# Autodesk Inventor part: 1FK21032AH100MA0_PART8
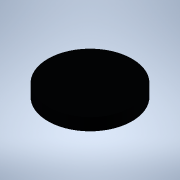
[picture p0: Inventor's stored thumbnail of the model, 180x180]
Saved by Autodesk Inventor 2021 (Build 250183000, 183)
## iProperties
Created: 2025-04
Part Number: 1FK21032AH100MA0_PART8
Material: Generic
Catalog Web Link: www.3dfindit.com
Description: -Servo synchronous motor
Document SubType Name: Modeling
Designer: psAdmin
Mass: 0.299142 g
Surface Area: 3.8585 cm^2
Volume: 0.299142 cm^3
Density: 1 g/cm^3
Appearance: PSOLRGB-38-46-56
Category: PARTsolutions
Title: 1FK21032AH100MA0_PART8
Author: Cadenas PARTsolutions
Comments: Servo synchronous motor
Sending System: PARTsolutions
Preprocessor: ST-DEVELOPER v19.3
PSOL_IDENT_0: {$CADENAS_DATA/23d-libs/siemens_ag/_cat_/12/33/1fk21032ah100ma0.prj},213 {VTYP=3D},{NB=1FK21032AH100
PSOL_IDENT_1: MA0_PART8},{LINA=1FK21032AH100MA0_PART8},{NN=1FK21032AH100MA0_PART8},{NOPRJ=TRUE},{DATE=19.08.2025 1
PSOL_IDENT_2: 4:00:27},{GEOMDATE=30.07.2025 02:02:58},{VERSION=},{LINEID=10},{WBVAR=},{WBNUMERIC=}  {NB=1FK21032AH
PSOL_IDENT_3: 100MA0_PART8},{LINA=1FK21032AH100MA0_PART8},{KT=DUMMY},{PREVIEW=../../../_pool_/d3/78/p_d211_xx_0093
PSOL_IDENT_4: 4j.png},{DESCSHORT=SIMOTICS S-1FK2 HD, SINAMICS S210 3AC 400V-480V, 0.59 Nm, 4500 rpm},{DESCLONG=SIM
PSOL_IDENT_5: OTICS S-1FK2 HD servo motor M0=0.64 Nm; PN = 0.28 kW at nN=4500 rpm (380-480 V); PN = 0.167 kW at nN=
PSOL_IDENT_6: 2500 rpm (200-240 V); with holding brake; degree of protection IP64; cylindrical shaft D14 x 30 mm;
PSOL_IDENT_7: absolute encoder 22-bit + 12-bit multiturn (encoder AM22DQC); with OCC interface; plug size M17, rot
PSOL_IDENT_8: atable; SIMOTICS S-1FK2 servomotorfor a wide range of uses in industrial environments. SIMOTICS S‑1F
PSOL_IDENT_9: K2 servomotors are compact synchronous motors with a high dynamic performance that set themselves ap
PSOL_IDENT_10: art as a result of their high power density, degree of protection and overload capability. The motor
PSOL_IDENT_11: s are available in two variants: as High Dynamic variant (highest dynamic performance as a result of
PSOL_IDENT_12: the low intrinsic moment of inertia for applications demanding a high dynamic performance with low
PSOL_IDENT_13: moved masses) - and as Compact variant (precise and stable closed-loop control for medium up to larg
PSOL_IDENT_14: e moved masses as a result of a medium intrinsic moment of inertia). SIMOTICSS‑1FK2 servomotors full
PSOL_IDENT_15: y exploit their strengths in a system with the SINAMICSS210 frequency converter and simple connectio
PSOL_IDENT_16: n using the one cable connection (OCC). Advantages include the short control and positioning times,
PSOL_IDENT_17: fast and precise correction of disturbing quantities as well as stable control with a high dynamic p
PSOL_IDENT_18: erformance. The servo motors can be configured to address a wide range of requirements. For example
PSOL_IDENT_19: with and without holding brake, IP64 or IP65 degree of protection, singleturn or multiturn absolute
PSOL_IDENT_20: encoders - to name just a few. Further, the servomotors are available in different shaft heights ext
PSOL_IDENT_21: ending from 20 to 100. A shaft sealing ring is available to achieve an IP65 degree of protection and
PSOL_IDENT_22: for subsequent mounting at the motor or as spare part. SIMOTICS - the optimum motor for each and ev
PSOL_IDENT_23: ery motion control application.},{INTNO=195125315563},{SUPPLIERALTNO=1FK2103-2AH10-0MA0},{MANUID=1FK
PSOL_IDENT_24: 21032AH100MA0},{MANUNAME=Siemens},{MANUTYPEDESC=SYNCHRONOUS MOTOR 1FK2 HD 0,64 NM},{AAU732=SIMOTICS}
PSOL_IDENT_25: ,{AAO057=S-1FK2},{AAU734=SIMOTICS S-1FK2 HD servo motor M0=0.64 Nm; PN = 0.28 kW at nN=4500 rpm (380
PSOL_IDENT_26: -480 V); PN = 0.167 kW at nN=2500 rpm (200-240 V); with holding brake; degree of protection IP64; cy
PSOL_IDENT_27: lindrical shaft D14 x 30 mm; absolute encoder 22-bit + 12-bit multiturn (encoder AM22DQC); with OCC
PSOL_IDENT_28: interface; plug size M17, rotatable;},{AAW338=SYNCHRONOUS MOTOR 1FK2 HD 0,64 NM},{AAO742=SIMOTICS},{
PSOL_IDENT_29: AAO663=4034106444723},{NOCUPEROU=1},{PRICEQUANTITY=1},{QUANTITYMIN=1},{QUANTITYINT=1},{CTN=85015100}
PSOL_IDENT_30: ,{COO=RO},{AAO676=1FK2103-2AH10-0MA0},{AAO677=Siemens AG},{ORDERUNIT=C62},{CONTENTUNIT=C62}
NB: 1FK21032AH100MA0_PART8
NT: Servo synchronous motor
NBSYN: $MANUID._PART8
LINA: 1FK21032AH100MA0_PART8
CATALOG: SIEMENS
PREVIEW: ../../../_pool_/d3/78/p_d211_xx_00934j.png
DESCSHORT: SIMOTICS S-1FK2 HD, SINAMICS S210 3AC 400V-480V, 0.59 Nm, 4500 rpm
DESCLONG: SIMOTICS S-1FK2 HD servo motor M0=0.64 Nm; PN = 0.28 kW at nN=4500 rpm (380-480 V); PN = 0.167 kW at nN=2500 rpm (200-240 V); with holding brake; degree of prot
INTNO: 195125315563
SUPPLIERALTNO: 1FK2103-2AH10-0MA0
MANUID: 1FK21032AH100MA0
MANUNAME: Siemens
MANUTYPEDESC: SYNCHRONOUS MOTOR 1FK2 HD 0,64 NM
AAU732: SIMOTICS
AAO057: S-1FK2
AAU734: SIMOTICS S-1FK2 HD servo motor M0=0.64 Nm; PN = 0.28 kW at nN=4500 rpm (380-480 V); PN = 0.167 kW at nN=2500 rpm (200-240 V); with holding brake; degree of prot
AAW338: SYNCHRONOUS MOTOR 1FK2 HD 0,64 NM
AAO742: SIMOTICS
AAO663: 4034106444723.0
NOCUPEROU: 1
PRICEQUANTITY: 1
QUANTITYMIN: 1
QUANTITYINT: 1
CTN: 85015100
COO: RO
ARTICLENO: 1FK21032AH100MA0_PART8
BOMINFO: 1FK21032AH100MA0_PART8
CREATOR: CADENAS GmbH
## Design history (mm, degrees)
feature "2025_04_17_15_06_16_0674"
body "Solid1"
